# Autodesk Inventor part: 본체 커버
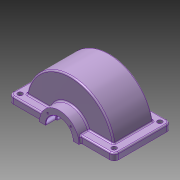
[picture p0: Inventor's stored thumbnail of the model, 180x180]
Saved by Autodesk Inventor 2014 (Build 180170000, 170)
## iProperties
Created: 2023-06
Part Number: 본체 커버
Material: 알루미늄 6061
Document SubType Name: Modeling
Designer: mdu-01
Density: 2.71 g/cm^3
Appearance: 알루미늄 - 평지(1)
Mass: 2296.01 g
Surface Area: 1364.02 cm^2
Volume: 847.238 cm^3
Author: mdu-01
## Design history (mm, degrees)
sketch "스케치1"
  geometry: L1 (0, 70)-(0, -70); L2 (0, 70)-(45, 70); L3 (45, 70)-(45, 45); L4 (45, 45)-(100, 45); L5 (0, 0)-(100, 0); L6 (0, -70)-(45, -70); L7 (45, -70)-(45, -45); L8 (45, -45)-(100, -45); L9 (100, 45)-(100, -45); 1 further point
  constraints: 18 end point, 3 perpendicular, 3 symmetric about line, 2 midpoint, 2 parallel, 1 coincident, 1 vertical
  dimensions: "d0" = 140 distance of L1.start L1.end; "d1" = 90 diameter of L3 L1; "d2" = 90 distance between parallel lines of L8 L4; "d3" = 200 diameter of L9 L1
revolve "회전1" sketch "스케치1" stored, may be unused: angle "d4" = 180 deg
sketch "스케치2"
  geometry: L1 (-10, -110)-(210, -110); L2 (220, -100)-(220, 10); L3 (210, 20)-(-10, 20); L4 (-20, 10)-(-20, -100); L5 (-20, -110)-(220, 20); L6 (220, -110)-(-20, 20); A1 r 10 centre (-10, 10) between (-10, 20) and (-20, 10); A2 r 10 centre (210, 10) between (220, 10) and (210, 20); A3 r 10 centre (210, -100) between (210, -110) and (220, -100); A4 r 10 centre (-10, -100) between (-20, -100) and (-10, -110); 1 further point
  constraints: 12 end point, 8 point on circle, 8 point on line, 8 tangent, 4 centre point, 3 equal radius, 2 midpoint, 2 parallel, 1 horizontal, 1 perpendicular
  dimensions: "d5" = 240 distance of L6.end L5.end; "d6" = 130 distance of L5.end L6.start; "d7" = 10 radius of A1
extrude "돌출1" join sketch "스케치2" distance "d8" = 15; taper "d9" = 0 deg
sketch "스케치3"
  geometry: L1 (0, 70)-(45, 70) reference; L2 (0, -70)-(45, -70) reference; L3 (0, 70)-(0, -70); L4 (31, 70)-(31, 48); L5 (30, 47)-(27.5, 47); L6 (27.5, 47)-(27.5, 32); L7 (27.5, 32)-(87, 32); L8 (0, 0)-(92.097, 0); L9 (31, -70)-(31, -48); L10 (30, -47)-(27.5, -47); L11 (27.5, -47)-(27.5, -32); L12 (27.5, -32)-(87, -32); L13 (87, 32)-(87, -32); L14 (0, 70)-(31, 70); L15 (0, -70)-(31, -70); A1 r 1 centre (30, 48) between (30, 47) and (31, 48); A2 r 1 centre (30, -48) between (31, -48) and (30, -47); 2 further points
  constraints: 26 end point, 5 point on line, 5 symmetric about line, 4 parallel, 4 point on circle, 4 tangent, 3 perpendicular, 2 centre point, 2 collinear, 1 equal radius
  dimensions: "d10" = 1 radius of A1; "d11" = 62 diameter of L4 L3; "d12" = 23 distance between parallel lines of L1 L5; "d13" = 64 distance between parallel lines of L12 L7; "d14" = 55 diameter of L6 L3; "d15" = 87 distance between parallel lines of L13 L3
revolve "회전2" sketch "스케치3" stored, may be unused: angle "d16" = 180 deg
fillet "모깎기1" dims "d17" = 3
fillet "모깎기2" dims "d18" = 3
sketch "스케치4"
  geometry: L1 (-7, -7)-(207, -7); L2 (207, -7)-(207, 97); L3 (207, 97)-(-7, 97); L4 (-7, 97)-(-7, -7); L5 (-7, -7)-(207, 97); L6 (207, -7)-(-7, 97); 1 further point
  constraints: 12 end point, 2 midpoint, 2 parallel, 1 horizontal, 1 perpendicular
  dimensions: "d19" = 214 distance of L3.end L2.end; "d20" = 104 distance of L2.end L1.end
hole "구멍1" sketch "스케치4" at (207, -7), (-7, -7), (207, 97), (-7, 97) diameter "d21" = 6.6; stored, may be unused: countersink angle "d25" = 90 deg, drill point angle "d27" = 118 deg; dims "d22" = 6, "d23" = 11, "d24" = 6.8, "d26" = 8
sketch "스케치5"
  geometry: L1 (-26.163, 26.163)-(26.163, 26.163); L2 (26.163, 26.163)-(26.163, -26.163); L3 (26.163, -26.163)-(-26.163, -26.163); L4 (-26.163, -26.163)-(-26.163, 26.163); A1 r 37 centre (0, 0) between (-26.163, 26.163) and (26.163, -26.163); 1 further point
  constraints: 8 end point, 3 point on circle, 2 parallel, 2 perpendicular, 1 centre point, 1 coincident, 1 horizontal
  dimensions: "d28" = 74 diameter of A1
hole "구멍2" sketch "스케치5" at (-26.163, 26.163), (26.163, 26.163) diameter "d29" = 4.134; stored, may be unused: countersink angle "d33" = 90 deg, drill point angle "d35" = 118 deg; dims "d30" = 10, "d31" = 11, "d32" = 6.8, "d34" = 12
chamfer "모따기1" distance "d36" = 1; stored, may be unused: second distance "d37" = 2, angle "d38" = 45 deg
node "솔리드1"
mirror "대칭1"
